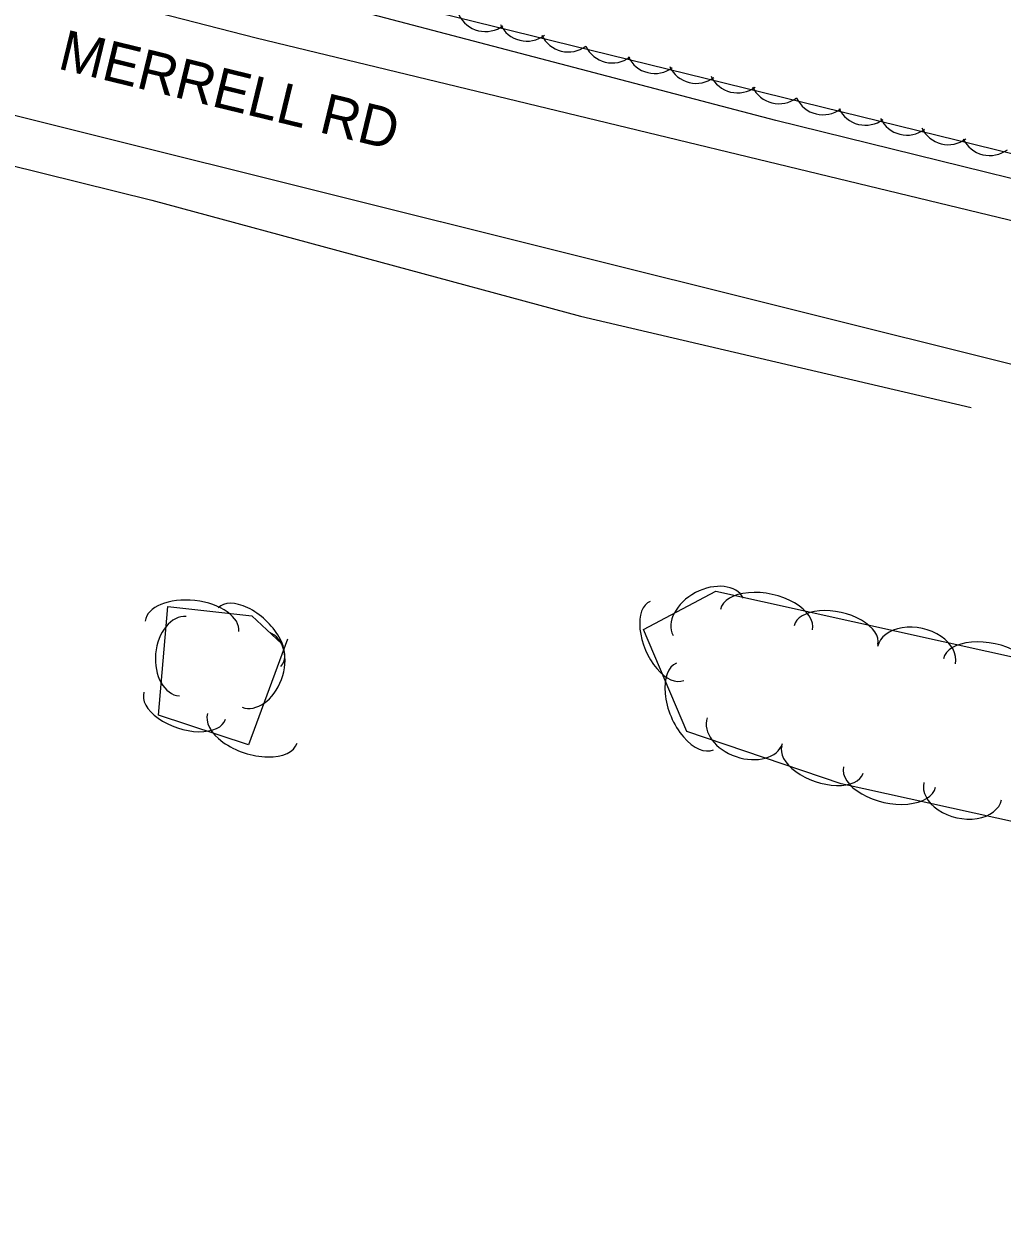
# Model space of a CAD drawing. Extents: x 1441650 to 1491889, y 345904 to 358319.
# Drawn here: x 1450847.8 to 1450969.6, y 353016.3 to 353164.2 of the extents above; entities that cross this region are included whole.
import ezdxf

# ---------------------------------------------------------------- set-up
doc = ezdxf.new("R2010")
doc.units = 0
for name, color, linetype in [('S_GRAVEL_ROAD', 7, 'Continuous'), ('S_GRAVEL_ROAD_ANNOT', 7, 'Continuous'), ('S_STREAM', 7, 'Continuous'), ('S_TREE', 7, 'Continuous')]:
    doc.layers.add(name, color=color, linetype=linetype)

msp = doc.modelspace()

# ---------------------------------------------------------------- linework, layer by layer
at = {"layer": 'S_GRAVEL_ROAD'}
for points in [[(1450240.59, 353319.75), (1450442.31, 353269.26), (1450609.24, 353228.48), (1450731.76, 353199.64), (1450876.75, 353162.42), (1450990.38, 353134.97), (1450995.57, 353133.86)], [(1450991.32, 353117.23), (1450972.29, 353121.41), (1450827.01, 353157.66), (1450719.85, 353183.96), (1450604.61, 353212.14), (1450498.35, 353237.72), (1450326.23, 353280.06), (1450221.98, 353305.71)]]:
    msp.add_lwpolyline(points, dxfattribs=at)
at = {"layer": 'S_STREAM'}
for points in [[(1450996.61, 353138.53), (1450941.42, 353152.13), (1450853.49, 353175.25), (1450758.66, 353198.82), (1450692.72, 353213.84)], [(1450642.61, 353196.85), (1450750.16, 353170.37), (1450863.74, 353142.23), (1450917.08, 353127.79), (1450965.72, 353116.46)]]:
    msp.add_lwpolyline(points, dxfattribs=at)
at = {"layer": 'S_TREE'}
for points in [[(1450707.94, 353249.81), (1450759.07, 353233.17), (1450809.24, 353221.54), (1450849.47, 353212.54), (1450911.9, 353197.86), (1450965.9, 353185.2), (1451005.19, 353176.39), (1451020.08, 353165.76), (1451019.45, 353153.91), (1451024.67, 353143.17), (1451042.11, 353143.37), (1451059, 353143.19), (1451063.29, 353135.69), (1451045.59, 353133.69), (1450995.11, 353142.03), (1450899.16, 353165.59), (1450810.82, 353186.18), (1450727.78, 353208.37)], [(1450993.07, 353050.56), (1450971.72, 353064.73), (1450949.52, 353069.64), (1450930.35, 353076.16), (1450924.94, 353088.83), (1450933.94, 353093.61), (1451018.44, 353074.91), (1451032.98, 353067.04), (1451039.35, 353042.88), (1451034.38, 353017.72), (1451017.57, 353016.35), (1451005.74, 353033.25), (1450993.14, 353051.92)], [(1450880.65, 353087.62), (1450875.78, 353074.47), (1450864.57, 353078.19), (1450865.75, 353091.69), (1450876.21, 353090.51), (1450879.94, 353087.03)]]:
    msp.add_lwpolyline(points, dxfattribs=at)
for centre, major_axis, ratio, start_param, end_param in [((1450905.26, 353166.83), (3.55, -0.81), 0.997144, 3.808192, 5.581393), ((1450910.41, 353165.64), (3.55, -0.81), 0.997144, 3.808192, 5.581393), ((1450915.57, 353164.29), (3.55, -0.81), 0.997144, 3.808192, 5.581393), ((1450921.05, 353162.92), (3.55, -0.81), 0.997144, 3.808192, 5.581393), ((1450926.33, 353161.62), (3.55, -0.81), 0.997144, 3.808192, 5.581393), ((1450931.49, 353160.39), (3.55, -0.81), 0.997144, 3.808192, 5.581393), ((1450936.64, 353159.2), (3.55, -0.81), 0.997144, 3.808192, 5.581393), ((1450941.8, 353157.85), (3.55, -0.81), 0.997144, 3.808192, 5.581393), ((1450947.28, 353156.48), (3.55, -0.81), 0.997144, 3.808192, 5.581393), ((1450952.56, 353155.18), (3.55, -0.81), 0.997144, 3.808192, 5.581393), ((1450957.72, 353153.95), (3.55, -0.81), 0.997144, 3.808192, 5.581393), ((1450962.87, 353152.76), (3.55, -0.81), 0.997144, 3.808192, 5.581393), ((1450968.03, 353151.41), (3.55, -0.81), 0.997144, 3.808192, 5.581393), ((1450933, 353090.41), (-4.38, -2.32), 0.685279, 3.141593, 6.283185), ((1450868.75, 353089.22), (-5.83, 0.66), 0.550055, 3.141576, 6.283168), ((1450875.92, 353087.88), (-3.9, 3.64), 0.542107, 3.140613, 6.282206), ((1450940.25, 353090.04), (-5.73, 1.27), 0.550033, 3.14159, 6.283183), ((1450927.85, 353087.41), (2.1, -4.92), 0.540682, 3.141596, 6.283189), ((1450948.9, 353088.12), (-5.22, 1.16), 0.540653, 3.14159, 6.283183), ((1450867.6, 353085.5), (-0.43, -4.94), 0.685224, 3.141593, 6.283185), ((1450958.91, 353085.64), (-4.84, 1.07), 0.685252, 3.141588, 6.283181), ((1450876.7, 353083.8), (1.72, 4.65), 0.685314, 3.141373, 6.282965), ((1450968, 353083.9), (-5.73, 1.27), 0.550033, 3.14159, 6.283183), ((1450931.34, 353079.26), (2.3, -5.4), 0.550062, 3.141596, 6.283189), ((1450867.85, 353079.34), (5.08, -1.68), 0.540657, 3.141618, 6.283211), ((1450876.26, 353076.55), (5.57, -1.85), 0.550037, 3.141619, 6.283212), ((1450937.55, 353076.23), (4.69, -1.6), 0.685262, 3.141683, 6.283275), ((1450947.22, 353072.66), (5.06, -1.72), 0.540661, 3.141646, 6.283239), ((1450955.56, 353070.48), (5.73, -1.27), 0.550038, 3.141638, 6.283231), ((1450964.66, 353068.73), (4.84, -1.07), 0.685259, 3.141667, 6.28326)]:
    msp.add_ellipse(centre, major_axis=major_axis, ratio=ratio, start_param=start_param, end_param=end_param, dxfattribs=at)

# ---------------------------------------------------------------- texts
at = {"layer": 'S_GRAVEL_ROAD_ANNOT'}
msp.add_text('MERRELL RD', height=5, rotation=346.3315, dxfattribs=at).set_placement((1450851.9, 353158.62))

doc.saveas('drawing.dxf')
